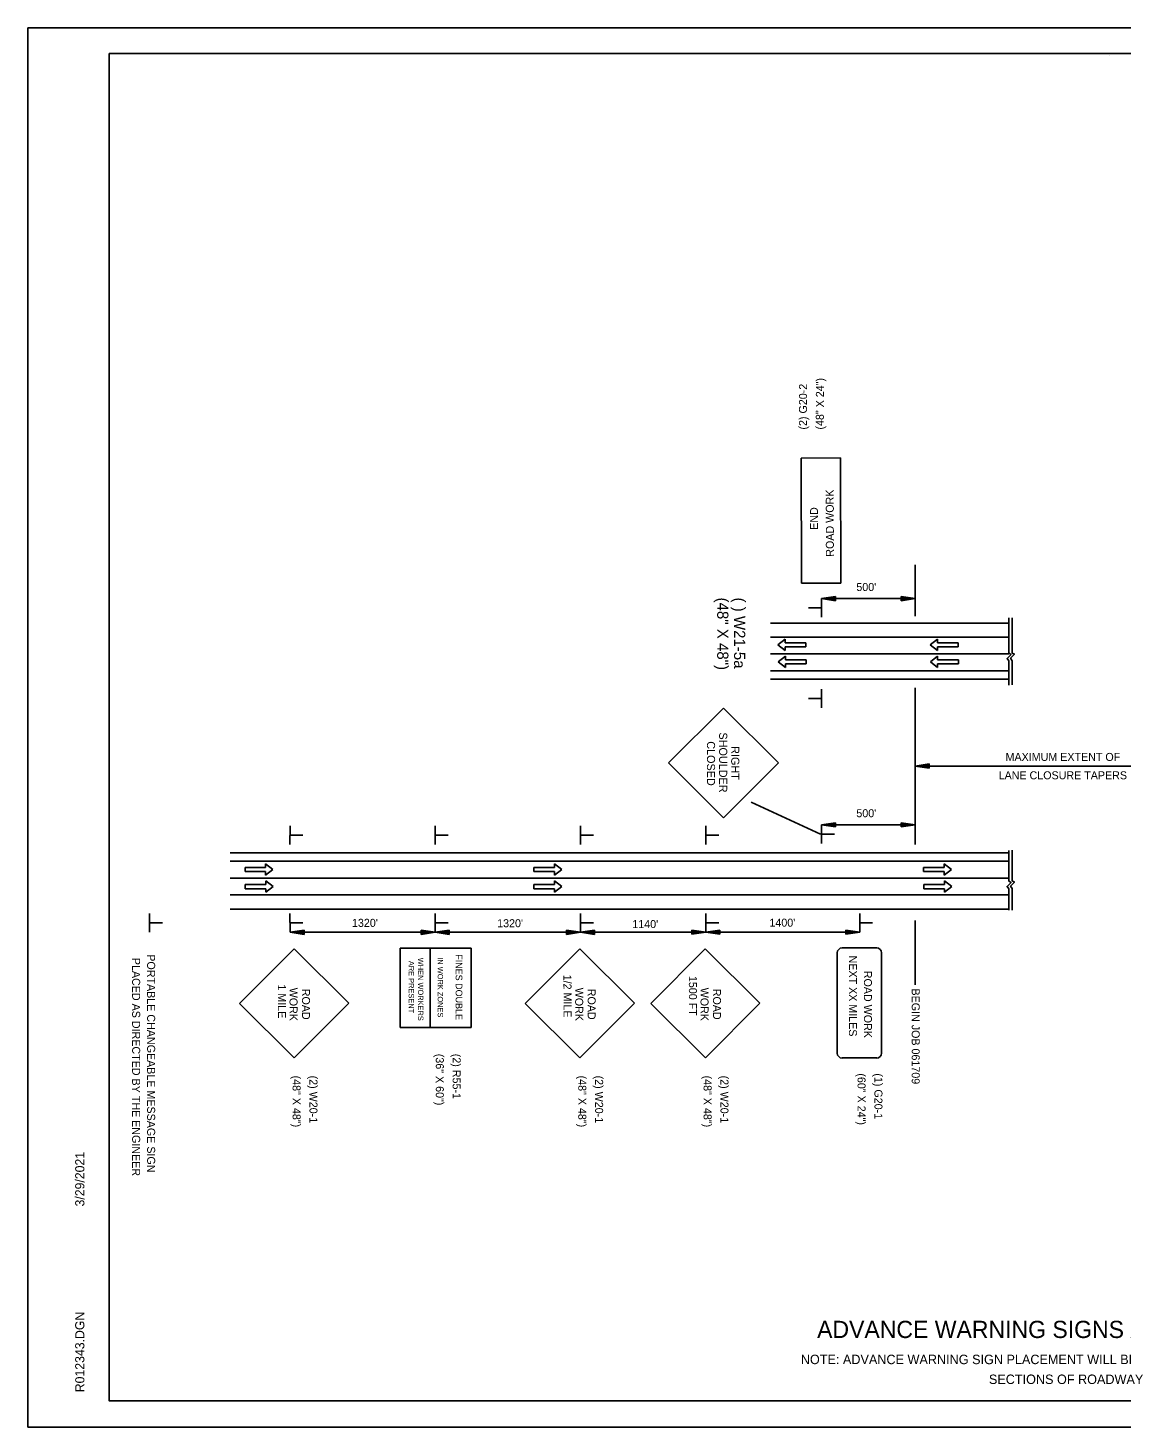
# Model space of a CAD drawing. Extents: x 1397271 to 1411271, y 376395 to 377888.
# Drawn here: x 1397271 to 1398438, y 376395 to 377888 of the extents above; entities that cross this region are included whole.
import ezdxf

# ---------------------------------------------------------------- set-up
doc = ezdxf.new("R2010")
doc.units = 0
for name, color, linetype in [('Default', 7, 'Continuous'), ('R_Border', 7, 'Continuous'), ('R_Draft', 7, 'Continuous'), ('R_MOT', 7, 'Continuous'), ('R_No Plot', 7, 'Continuous')]:
    doc.layers.add(name, color=color, linetype=linetype)

msp = doc.modelspace()

# ---------------------------------------------------------------- linework, layer by layer
at = {"layer": 'Default'}
for p, q in [((1398218.1, 377260.1), (1398218.1, 377315.1)), ((1398118.1, 377278.9), (1398218.1, 377278.9)), ((1398063.8, 377252.8), (1398318.1, 377252.8)), ((1398318.1, 377220.5), (1398318.1, 377258.3)), ((1398318.1, 377220.5), (1398318.1, 377258.3)), ((1398321.8, 377220.8), (1398321.8, 377258.5)), ((1398321.8, 377220.8), (1398321.8, 377258.5)), ((1398063.8, 377237.8), (1398318.1, 377237.8)), ((1398071.6, 377229.5), (1398079.4, 377235.5)), ((1398079.4, 377231.8), (1398079.4, 377235.5)), ((1398079.4, 377231.8), (1398101.5, 377231.8)), ((1398101.5, 377227.3), (1398101.5, 377231.8)), ((1398234.2, 377229.5), (1398242, 377235.5)), ((1398242, 377231.8), (1398242, 377235.5)), ((1398242, 377231.8), (1398264, 377231.8)), ((1398264, 377227.3), (1398264, 377231.8)), ((1398063.8, 377219.8), (1398318.1, 377219.8)), ((1398079.4, 377223.5), (1398071.6, 377229.5)), ((1398071.8, 377211.4), (1398079.5, 377217.4)), ((1398079.4, 377227.3), (1398101.5, 377227.3)), ((1398079.4, 377223.5), (1398079.4, 377227.3)), ((1398079.5, 377213.6), (1398079.5, 377217.4)), ((1398242, 377223.5), (1398234.2, 377229.5)), ((1398234.3, 377211.4), (1398242.1, 377217.4)), ((1398242, 377227.3), (1398264, 377227.3)), ((1398242, 377223.5), (1398242, 377227.3)), ((1398242.1, 377213.6), (1398242.1, 377217.4)), ((1398063.8, 377201.8), (1398318.1, 377201.8)), ((1398079.5, 377205.4), (1398071.8, 377211.4)), ((1398079.5, 377213.6), (1398101.6, 377213.6)), ((1398079.5, 377209.1), (1398101.6, 377209.1)), ((1398079.5, 377205.4), (1398079.5, 377209.1)), ((1398101.6, 377209.1), (1398101.6, 377213.6)), ((1398242.1, 377205.4), (1398234.3, 377211.4)), ((1398242.1, 377213.6), (1398264.2, 377213.6)), ((1398242.1, 377209.1), (1398264.2, 377209.1)), ((1398242.1, 377205.4), (1398242.1, 377209.1)), ((1398264.2, 377209.1), (1398264.2, 377213.6)), ((1398318.1, 377186.4), (1398318.1, 377212.3)), ((1398318.1, 377186.4), (1398318.1, 377212.3)), ((1398321.8, 377186.7), (1398321.8, 377212.6)), ((1398321.8, 377186.7), (1398321.8, 377212.6)), ((1398063.8, 377192.8), (1398318.1, 377192.8)), ((1398218.1, 377183.8), (1398218.1, 377016.5)), ((1398218.1, 377100.1), (1398545.2, 377100.1)), ((1398117, 377027.5), (1398043, 377061.5)), ((1398118.1, 377037.4), (1398218.1, 377037.4)), ((1397486.9, 377007.5), (1398318.1, 377007.5)), ((1398318.1, 376977.3), (1398318.1, 377010.1)), ((1398321.8, 376977.6), (1398321.8, 377010.4)), ((1397486.9, 376998.5), (1398318.1, 376998.5)), ((1397524.6, 376991.9), (1397502.6, 376991.9)), ((1397502.6, 376991.9), (1397502.6, 376987.4)), ((1397524.6, 376995.6), (1397524.6, 376991.9)), ((1397524.6, 376995.6), (1397532.4, 376989.6)), ((1397832.9, 376991.9), (1397810.9, 376991.9)), ((1397810.9, 376991.9), (1397810.9, 376987.4)), ((1397832.9, 376995.6), (1397832.9, 376991.9)), ((1397832.9, 376995.6), (1397840.7, 376989.6)), ((1398249.2, 376991.9), (1398227.1, 376991.9)), ((1398227.1, 376991.9), (1398227.1, 376987.4)), ((1398249.2, 376995.6), (1398249.2, 376991.9)), ((1398249.2, 376995.6), (1398257, 376989.6)), ((1397486.9, 376980.5), (1398318.1, 376980.5)), ((1397524.6, 376987.4), (1397502.6, 376987.4)), ((1397532.4, 376989.6), (1397524.6, 376983.6)), ((1397524.6, 376987.4), (1397524.6, 376983.6)), ((1397524.7, 376977.5), (1397524.7, 376973.7)), ((1397524.7, 376977.5), (1397532.5, 376971.5)), ((1397832.9, 376987.4), (1397810.9, 376987.4)), ((1397840.7, 376989.6), (1397832.9, 376983.6)), ((1397832.9, 376987.4), (1397832.9, 376983.6)), ((1397833.1, 376977.5), (1397833.1, 376973.7)), ((1397833.1, 376977.5), (1397840.8, 376971.5)), ((1398249.2, 376987.4), (1398227.1, 376987.4)), ((1398257, 376989.6), (1398249.2, 376983.6)), ((1398249.2, 376987.4), (1398249.2, 376983.6)), ((1398249.3, 376977.5), (1398249.3, 376973.7)), ((1398249.3, 376977.5), (1398257.1, 376971.5)), ((1397486.9, 376962.5), (1398318.1, 376962.5)), ((1397524.7, 376973.7), (1397502.7, 376973.7)), ((1397502.7, 376973.7), (1397502.7, 376969.2)), ((1397524.7, 376969.2), (1397502.7, 376969.2)), ((1397532.5, 376971.5), (1397524.7, 376965.5)), ((1397524.7, 376969.2), (1397524.7, 376965.5)), ((1397833.1, 376973.7), (1397811, 376973.7)), ((1397811, 376973.7), (1397811, 376969.2)), ((1397833.1, 376969.2), (1397811, 376969.2)), ((1397840.8, 376971.5), (1397833.1, 376965.5)), ((1397833.1, 376969.2), (1397833.1, 376965.5)), ((1398249.3, 376973.7), (1398227.3, 376973.7)), ((1398227.3, 376973.7), (1398227.3, 376969.2)), ((1398249.3, 376969.2), (1398227.3, 376969.2)), ((1398257.1, 376971.5), (1398249.3, 376965.5)), ((1398249.3, 376969.2), (1398249.3, 376965.5)), ((1398318.1, 376946.2), (1398318.1, 376969.1)), ((1398321.8, 376946.4), (1398321.8, 376969.3)), ((1397486.9, 376947.5), (1398318.1, 376947.5)), ((1398218.1, 376935.4), (1398218.1, 376866.6)), ((1397705.7, 376922.8), (1397550.7, 376922.8)), ((1397860.7, 376922.8), (1397705.7, 376922.8)), ((1397994.5, 376922.8), (1397860.7, 376922.8)), ((1398158.9, 376922.9), (1397994.5, 376922.8))]:
    msp.add_line(p, q, dxfattribs=at)
for points in [[(1398318.1, 377220.5), (1398320.5, 377219.2), (1398316.3, 377214.9), (1398318.1, 377212.3)], [(1398318.1, 377220.5), (1398320.5, 377219.2), (1398316.3, 377214.9), (1398318.1, 377212.3)], [(1398321.8, 377220.8), (1398324.1, 377219.4), (1398319.9, 377215.2), (1398321.8, 377212.6)], [(1398321.8, 377220.8), (1398324.1, 377219.4), (1398319.9, 377215.2), (1398321.8, 377212.6)], [(1398318.1, 376977.3), (1398320.5, 376975.9), (1398316.3, 376971.7), (1398318.1, 376969.1)], [(1398321.8, 376977.6), (1398324.1, 376976.2), (1398319.9, 376971.9), (1398321.8, 376969.3)]]:
    msp.add_lwpolyline(points, dxfattribs=at)
at = {"layer": 'R_Border'}
for p, q in [((1397357.7, 377860.7), (1399571, 377860.7)), ((1397357.7, 376422.5), (1397357.7, 377860.7)), ((1398425.4, 377858.9), (1398425.4, 377858.9)), ((1398425.4, 377858.9), (1398425.4, 377858.9)), ((1397357.7, 376422.5), (1397357.7, 376422.5)), ((1399571, 376422.5), (1397357.7, 376422.5))]:
    msp.add_line(p, q, dxfattribs=at)
at = {"layer": 'R_Draft'}
for p, q in [((1398133.1, 377281.1), (1398118.1, 377278.9)), ((1398133.1, 377276.6), (1398118.1, 377278.9)), ((1398133.1, 377280.7), (1398120.6, 377278.9)), ((1398133.1, 377277), (1398120.6, 377278.9)), ((1398133.1, 377280.4), (1398123.2, 377278.9)), ((1398133.1, 377277.4), (1398123.2, 377278.9)), ((1398133.1, 377280), (1398125.7, 377278.9)), ((1398133.1, 377277.8), (1398125.7, 377278.9)), ((1398133.1, 377279.6), (1398128.2, 377278.9)), ((1398133.1, 377278.1), (1398128.2, 377278.9)), ((1398133.1, 377279.2), (1398130.7, 377278.9)), ((1398133.1, 377278.5), (1398130.7, 377278.9)), ((1398133.1, 377276.6), (1398133.1, 377281.1)), ((1398203.1, 377281.1), (1398218.1, 377278.9)), ((1398203.1, 377281.1), (1398203.1, 377276.6)), ((1398203.1, 377280.7), (1398215.6, 377278.9)), ((1398203.1, 377280.4), (1398213, 377278.9)), ((1398203.1, 377280), (1398210.5, 377278.9)), ((1398203.1, 377279.6), (1398208, 377278.9)), ((1398203.1, 377279.2), (1398205.5, 377278.9)), ((1398203.1, 377276.6), (1398218.1, 377278.9)), ((1398203.1, 377278.1), (1398208, 377278.9)), ((1398203.1, 377277.4), (1398213, 377278.9)), ((1398203.1, 377277), (1398215.6, 377278.9)), ((1398203.1, 377277.8), (1398210.5, 377278.9)), ((1398203.1, 377278.5), (1398205.5, 377278.9)), ((1398233.1, 377102.4), (1398218.1, 377100.1)), ((1398233.1, 377097.9), (1398218.1, 377100.1)), ((1398233.1, 377102), (1398220.6, 377100.1)), ((1398233.1, 377098.3), (1398220.6, 377100.1)), ((1398233.1, 377101.6), (1398223.2, 377100.1)), ((1398233.1, 377098.6), (1398223.2, 377100.1)), ((1398233.1, 377101.3), (1398225.7, 377100.1)), ((1398233.1, 377099), (1398225.7, 377100.1)), ((1398233.1, 377100.9), (1398228.3, 377100.1)), ((1398233.1, 377099.4), (1398228.3, 377100.1)), ((1398233.1, 377100.5), (1398230.8, 377100.1)), ((1398233.1, 377099.8), (1398230.8, 377100.1)), ((1398233.1, 377097.9), (1398233.1, 377102.4)), ((1398133.1, 377039.6), (1398118.1, 377037.4)), ((1398133.1, 377035.1), (1398118.1, 377037.4)), ((1398133.1, 377039.3), (1398120.6, 377037.4)), ((1398133.1, 377035.5), (1398120.6, 377037.4)), ((1398133.1, 377038.9), (1398123.2, 377037.4)), ((1398133.1, 377035.9), (1398123.2, 377037.4)), ((1398133.1, 377038.5), (1398125.7, 377037.4)), ((1398133.1, 377036.3), (1398125.7, 377037.4)), ((1398133.1, 377038.1), (1398128.2, 377037.4)), ((1398133.1, 377036.7), (1398128.2, 377037.4)), ((1398133.1, 377037.7), (1398130.7, 377037.4)), ((1398133.1, 377037), (1398130.7, 377037.4)), ((1398133.1, 377035.1), (1398133.1, 377039.6)), ((1398203.1, 377039.6), (1398218.1, 377037.4)), ((1398203.1, 377039.6), (1398203.1, 377035.1)), ((1398203.1, 377039.3), (1398215.6, 377037.4)), ((1398203.1, 377038.9), (1398213, 377037.4)), ((1398203.1, 377038.5), (1398210.5, 377037.4)), ((1398203.1, 377038.1), (1398208, 377037.4)), ((1398203.1, 377037.7), (1398205.5, 377037.4)), ((1398203.1, 377035.1), (1398218.1, 377037.4)), ((1398203.1, 377036.7), (1398208, 377037.4)), ((1398203.1, 377035.9), (1398213, 377037.4)), ((1398203.1, 377035.5), (1398215.6, 377037.4)), ((1398203.1, 377036.3), (1398210.5, 377037.4)), ((1398203.1, 377037), (1398205.5, 377037.4)), ((1397565.7, 376925), (1397550.7, 376922.8)), ((1397565.7, 376920.5), (1397550.7, 376922.8)), ((1397565.7, 376924.7), (1397553.2, 376922.8)), ((1397565.7, 376920.9), (1397553.2, 376922.8)), ((1397565.7, 376924.3), (1397555.8, 376922.8)), ((1397565.7, 376921.3), (1397555.8, 376922.8)), ((1397565.7, 376923.9), (1397558.3, 376922.8)), ((1397565.7, 376921.7), (1397558.3, 376922.8)), ((1397565.7, 376923.5), (1397560.8, 376922.8)), ((1397565.7, 376922.1), (1397560.8, 376922.8)), ((1397565.7, 376923.1), (1397563.3, 376922.8)), ((1397565.7, 376922.4), (1397563.3, 376922.8)), ((1397565.7, 376920.5), (1397565.7, 376925)), ((1397690.7, 376925), (1397705.7, 376922.8)), ((1397690.7, 376925), (1397690.7, 376920.5)), ((1397690.7, 376924.7), (1397703.2, 376922.8)), ((1397690.7, 376924.3), (1397700.6, 376922.8)), ((1397690.7, 376923.9), (1397698.1, 376922.8)), ((1397690.7, 376923.5), (1397695.6, 376922.8)), ((1397690.7, 376923.1), (1397693.1, 376922.8)), ((1397690.7, 376920.5), (1397705.7, 376922.8)), ((1397690.7, 376922.1), (1397695.6, 376922.8)), ((1397690.7, 376921.3), (1397700.6, 376922.8)), ((1397690.7, 376920.9), (1397703.2, 376922.8)), ((1397690.7, 376921.7), (1397698.1, 376922.8)), ((1397690.7, 376922.4), (1397693.1, 376922.8)), ((1397720.7, 376925), (1397705.7, 376922.8)), ((1397720.7, 376920.5), (1397705.7, 376922.8)), ((1397720.7, 376924.7), (1397708.2, 376922.8)), ((1397720.7, 376920.9), (1397708.2, 376922.8)), ((1397720.7, 376924.3), (1397710.8, 376922.8)), ((1397720.7, 376921.3), (1397710.8, 376922.8)), ((1397720.7, 376923.9), (1397713.3, 376922.8)), ((1397720.7, 376921.7), (1397713.3, 376922.8)), ((1397720.7, 376923.5), (1397715.8, 376922.8)), ((1397720.7, 376922.1), (1397715.8, 376922.8)), ((1397720.7, 376923.1), (1397718.3, 376922.8)), ((1397720.7, 376922.4), (1397718.3, 376922.8)), ((1397720.7, 376920.5), (1397720.7, 376925)), ((1397845.7, 376925), (1397860.7, 376922.8)), ((1397845.7, 376925), (1397845.7, 376920.5)), ((1397845.7, 376924.7), (1397858.2, 376922.8)), ((1397845.7, 376924.3), (1397855.6, 376922.8)), ((1397845.7, 376923.9), (1397853.1, 376922.8)), ((1397845.7, 376923.5), (1397850.6, 376922.8)), ((1397845.7, 376923.1), (1397848.1, 376922.8)), ((1397845.7, 376920.5), (1397860.7, 376922.8)), ((1397845.7, 376922.1), (1397850.6, 376922.8)), ((1397845.7, 376921.3), (1397855.6, 376922.8)), ((1397845.7, 376920.9), (1397858.2, 376922.8)), ((1397845.7, 376921.7), (1397853.1, 376922.8)), ((1397845.7, 376922.4), (1397848.1, 376922.8)), ((1397875.7, 376925), (1397860.7, 376922.8)), ((1397875.7, 376920.5), (1397860.7, 376922.8)), ((1397875.7, 376924.7), (1397863.2, 376922.8)), ((1397875.7, 376920.9), (1397863.2, 376922.8)), ((1397875.7, 376924.3), (1397865.8, 376922.8)), ((1397875.7, 376921.3), (1397865.8, 376922.8)), ((1397875.7, 376923.9), (1397868.3, 376922.8)), ((1397875.7, 376921.7), (1397868.3, 376922.8)), ((1397875.7, 376923.5), (1397870.8, 376922.8)), ((1397875.7, 376922.1), (1397870.8, 376922.8)), ((1397875.7, 376923.1), (1397873.3, 376922.8)), ((1397875.7, 376922.4), (1397873.3, 376922.8)), ((1397875.7, 376920.5), (1397875.7, 376925)), ((1397979.5, 376925.1), (1397994.5, 376922.8)), ((1397979.5, 376925.1), (1397979.5, 376920.6)), ((1397979.5, 376924.7), (1397992, 376922.8)), ((1397979.5, 376924.3), (1397989.5, 376922.8)), ((1397979.5, 376923.9), (1397987, 376922.8)), ((1397979.5, 376923.6), (1397984.4, 376922.8)), ((1397979.5, 376923.2), (1397981.9, 376922.8)), ((1397979.5, 376920.6), (1397994.5, 376922.8)), ((1397979.5, 376922.1), (1397984.4, 376922.8)), ((1397979.5, 376921.3), (1397989.5, 376922.8)), ((1397979.5, 376921), (1397992, 376922.8)), ((1397979.5, 376921.7), (1397987, 376922.8)), ((1397979.5, 376922.5), (1397981.9, 376922.8)), ((1398009.5, 376925.1), (1397994.5, 376922.8)), ((1398009.5, 376920.6), (1397994.5, 376922.8)), ((1398009.5, 376924.7), (1397997.1, 376922.8)), ((1398009.5, 376921), (1397997.1, 376922.8)), ((1398009.5, 376924.3), (1397999.6, 376922.8)), ((1398009.5, 376921.3), (1397999.6, 376922.8)), ((1398009.5, 376923.9), (1398002.1, 376922.8)), ((1398009.5, 376921.7), (1398002.1, 376922.8)), ((1398009.5, 376923.6), (1398004.7, 376922.8)), ((1398009.5, 376922.1), (1398004.7, 376922.8)), ((1398009.5, 376923.2), (1398007.2, 376922.8)), ((1398009.5, 376922.5), (1398007.2, 376922.8)), ((1398009.5, 376920.6), (1398009.5, 376925.1)), ((1398143.9, 376925.1), (1398158.9, 376922.9)), ((1398143.9, 376925.1), (1398143.9, 376920.6)), ((1398143.9, 376924.7), (1398156.4, 376922.9)), ((1398143.9, 376924.4), (1398153.9, 376922.9)), ((1398143.9, 376924), (1398151.4, 376922.9)), ((1398143.9, 376923.6), (1398148.8, 376922.9)), ((1398143.9, 376923.2), (1398146.3, 376922.9)), ((1398143.9, 376920.6), (1398158.9, 376922.9)), ((1398143.9, 376922.1), (1398148.8, 376922.9)), ((1398143.9, 376921.4), (1398153.9, 376922.9)), ((1398143.9, 376921), (1398156.4, 376922.9)), ((1398143.9, 376921.7), (1398151.4, 376922.9)), ((1398143.9, 376922.5), (1398146.3, 376922.9))]:
    msp.add_line(p, q, dxfattribs=at)
at = {"layer": 'R_MOT'}
for p, q in [((1398138.4, 377429), (1398096.5, 377428.9)), ((1398096.5, 377428.9), (1398096.7, 377295.4)), ((1398138.4, 377429), (1398138.7, 377295.5)), ((1398138.7, 377295.5), (1398096.7, 377295.4)), ((1398118.1, 377278.9), (1398118.2, 377259)), ((1398118.2, 377269), (1398104.3, 377268.9)), ((1398118.2, 377172.2), (1398104.3, 377172.3)), ((1398118.1, 377162.4), (1398118.2, 377182.2)), ((1397954.8, 377103.4), (1398013.4, 377162.1)), ((1398072, 377103.4), (1398013.4, 377162.1)), ((1398013.4, 377044.8), (1397954.8, 377103.4)), ((1398013.4, 377044.8), (1398072, 377103.4)), ((1398118.1, 377037.4), (1398118, 377017.5)), ((1397550.7, 377036.3), (1397550.6, 377016.4)), ((1397550.6, 377026.4), (1397564.5, 377026.3)), ((1397705.7, 377036.3), (1397705.6, 377016.4)), ((1397705.6, 377026.4), (1397719.5, 377026.3)), ((1397860.7, 377036.3), (1397860.6, 377016.4)), ((1397860.6, 377026.4), (1397874.5, 377026.3)), ((1397994.5, 377036.2), (1397994.5, 377016.4)), ((1397994.5, 377026.3), (1398008.3, 377026.3)), ((1398118.1, 377027.5), (1398131.9, 377027.5)), ((1397400.7, 376922.8), (1397400.6, 376942.6)), ((1397400.6, 376932.7), (1397414.5, 376932.7)), ((1397550.7, 376922.8), (1397550.6, 376942.6)), ((1397550.6, 376932.7), (1397564.5, 376932.7)), ((1397705.7, 376922.8), (1397705.6, 376942.6)), ((1397705.6, 376932.7), (1397719.5, 376932.7)), ((1397860.7, 376922.8), (1397860.6, 376942.6)), ((1397860.6, 376932.7), (1397874.5, 376932.7)), ((1397994.5, 376922.8), (1397994.5, 376942.7)), ((1397994.5, 376932.7), (1398008.3, 376932.8)), ((1398158.9, 376922.9), (1398158.9, 376942.7)), ((1398158.9, 376932.7), (1398172.7, 376932.8)), ((1397496.8, 376846.7), (1397555, 376905.1)), ((1397613.3, 376846.9), (1397555, 376905.1)), ((1397700.1, 376821.2), (1397700.1, 376905.6)), ((1397801.8, 376846.7), (1397860, 376905.1)), ((1397918.3, 376846.9), (1397860, 376905.1)), ((1397935.7, 376846.7), (1397993.9, 376905.1)), ((1398052.2, 376846.9), (1397993.9, 376905.1)), ((1398140.1, 376906), (1398177, 376906)), ((1398134.9, 376793.6), (1398134.9, 376900.8)), ((1398182.1, 376793.6), (1398182.1, 376900.8)), ((1397555.2, 376788.5), (1397496.8, 376846.7)), ((1397555.2, 376788.5), (1397613.3, 376846.9)), ((1397860.2, 376788.5), (1397801.8, 376846.7)), ((1397860.2, 376788.5), (1397918.3, 376846.9)), ((1397994.1, 376788.6), (1397935.7, 376846.7)), ((1397994.1, 376788.6), (1398052.2, 376846.9)), ((1398140.1, 376788.5), (1398177, 376788.5))]:
    msp.add_line(p, q, dxfattribs=at)
msp.add_lwpolyline([(1397743.9, 376905.6), (1397668.4, 376905.6), (1397668.4, 376821.2), (1397743.9, 376821.2)], close=True, dxfattribs=at)
for centre, start, end in [((1398140.1, 376900.8), 90, 180), ((1398177, 376900.8), 0, 90), ((1398140.1, 376793.6), 180, 270), ((1398177, 376793.6), 270, 0)]:
    msp.add_arc(centre, 5.17, start, end, dxfattribs=at)
at = {"layer": 'R_No Plot'}
for p, q in [((1397270.9, 377888), (1399604.3, 377888)), ((1397270.9, 376394.6), (1399604.3, 376394.6))]:
    msp.add_line(p, q, dxfattribs=at)
for points in [[(1397270.9, 377888), (1399604.3, 377888), (1399604.3, 376394.6), (1397270.9, 376394.6)], [(1398995.2, 377860.7), (1398995.2, 377791.6), (1399245.3, 377791.6), (1399245.3, 377771.1), (1399407.7, 377771.1), (1399407.7, 377600.8), (1399571, 377600.8), (1399571, 376422.5), (1397357.7, 376422.5), (1397357.7, 377860.7)]]:
    msp.add_lwpolyline(points, close=True, dxfattribs=at)

# ---------------------------------------------------------------- texts
at = {"layer": 'Default'}
for s, height, p in [("500'", 8.54, (1398155.3, 377287)), ('MAXIMUM EXTENT OF ', 8.54, (1398314.6, 377105.6)), ('LANE CLOSURE TAPERS', 8.54, (1398307.2, 377086)), ("500'", 8.54, (1398155.3, 377045.5)), ("1320'", 8.54, (1397616.8, 376928.5)), ("1320'", 8.54, (1397771.8, 376928.1)), ("1140'", 8.54, (1397916.1, 376927.2)), ("1400'", 8.54, (1398062.5, 376928.7)), ('ADVANCE WARNING SIGNS AT JOB ENDS', 18.375, (1398113.4, 376489.6)), ('NOTE: ADVANCE WARNING SIGN PLACEMENT WILL BE IDENTICAL FOR 6-LANE', 10.087, (1398096, 376461.7)), ('SECTIONS OF ROADWAY', 10.087, (1398296.8, 376440.5))]:
    msp.add_text(s, height=height, dxfattribs=at).set_placement(p)
for s, p in [('PLACED AS DIRECTED BY THE ENGINEER', (1397382.1, 376895.4)), ('PORTABLE CHANGEABLE MESSAGE SIGN', (1397398.1, 376899.2)), ('BEGIN JOB 061709', (1398214.4, 376862.7))]:
    msp.add_text(s, height=8.54, rotation=270, dxfattribs=at).set_placement(p)
at = {"layer": 'R_Border'}
for s, p in [('3/29/2021', (1397331.1, 376630)), ('R012343.DGN', (1397331.1, 376431.7))]:
    msp.add_text(s, height=9.8, rotation=90, dxfattribs=at).set_placement(p)
at = {"layer": 'R_MOT'}
for s, height, rotation, p in [('(2) G20-2', 8.54, 89.7913, (1398102.5, 377459.3)), ('(48" X 24")', 8.54, 89.7913, (1398120.5, 377459.3)), ('ROAD WORK', 8.54, 90.0992, (1398131.3, 377323.6)), ('END', 8.54, 90.0992, (1398114.4, 377352.3)), ('(48" X 48")', 12, 270, (1398006.7, 377280)), ('( ) W21-5a', 12, 270, (1398024.7, 377280)), ('SHOULDER', 8.64, 270, (1398008.8, 377136)), ('CLOSED', 8.64, 270.0006, (1397995.8, 377126.6)), ('RIGHT', 8.64, 270.0004, (1398021.7, 377121.4)), ('ARE PRESENT', 5.731, 270, (1397677.3, 376892.2)), ('WHEN WORKERS', 5.731, 270, (1397687.3, 376895.5)), ('IN WORK ZONES', 5.73, 270, (1397708.3, 376896)), ('FINES DOUBLE', 7.164, 270, (1397727.5, 376899.3)), (' NEXT XX MILES', 8.54, 270, (1398147.4, 376901)), (' 1/2 MILE', 8.54, 270.0995, (1397842.6, 376880.6)), (' 1500 FT', 8.54, 270.0995, (1397976.5, 376879.3)), ('ROAD WORK', 8.54, 270, (1398163.4, 376881.6)), (' 1 MILE', 8.54, 270.0995, (1397537.7, 376870.2)), ('WORK', 8.54, 270.1003, (1397550.1, 376863.5)), ('ROAD', 8.54, 270.1004, (1397563.4, 376862.4)), ('WORK', 8.54, 270.1003, (1397855.1, 376863.5)), ('ROAD', 8.54, 270.1004, (1397868.4, 376862.4)), ('WORK', 8.54, 270.1003, (1397988.9, 376863.5)), ('ROAD', 8.54, 270.1004, (1398002.2, 376862.4)), ('(36" X 60")', 8.54, 270, (1397706.3, 376793)), ('(2) R55-1', 8.54, 270, (1397724.3, 376793)), ('(48" X 48")', 8.54, 270, (1397553.4, 376769.7)), ('(2) W20-1', 8.54, 270, (1397571.4, 376769.7)), ('(48" X 48")', 8.54, 270, (1397858.4, 376769.7)), ('(2) W20-1', 8.54, 270, (1397876.4, 376769.7)), ('(48" X 48")', 8.54, 270, (1397992.2, 376769.7)), ('(2) W20-1', 8.54, 270, (1398010.2, 376769.7)), ('(60" X 24")', 8.54, 270, (1398156.6, 376772.1)), ('(1) G20-1', 8.54, 270, (1398174.6, 376772.1))]:
    msp.add_text(s, height=height, rotation=rotation, dxfattribs=at).set_placement(p)

doc.saveas('drawing.dxf')
